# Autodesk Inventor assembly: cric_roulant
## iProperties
Shininess: 64.0
Length Units: 11269
Angle Units: 11279
Time Units: 11290
Mass Units: 11283
Length Display Precision: 3
Angle Display Precision: 2
Compacted: True
Created: 2005-04
Part Number: cric_roulant
Document SubType Name: Assembly
Designer: thchene
Density: 0.0
Volumn: 0.0
Area: 0.0
PropertySet Name: Model Information
Control State: 0
Master: False
Checked Out: False
Author: thchene
